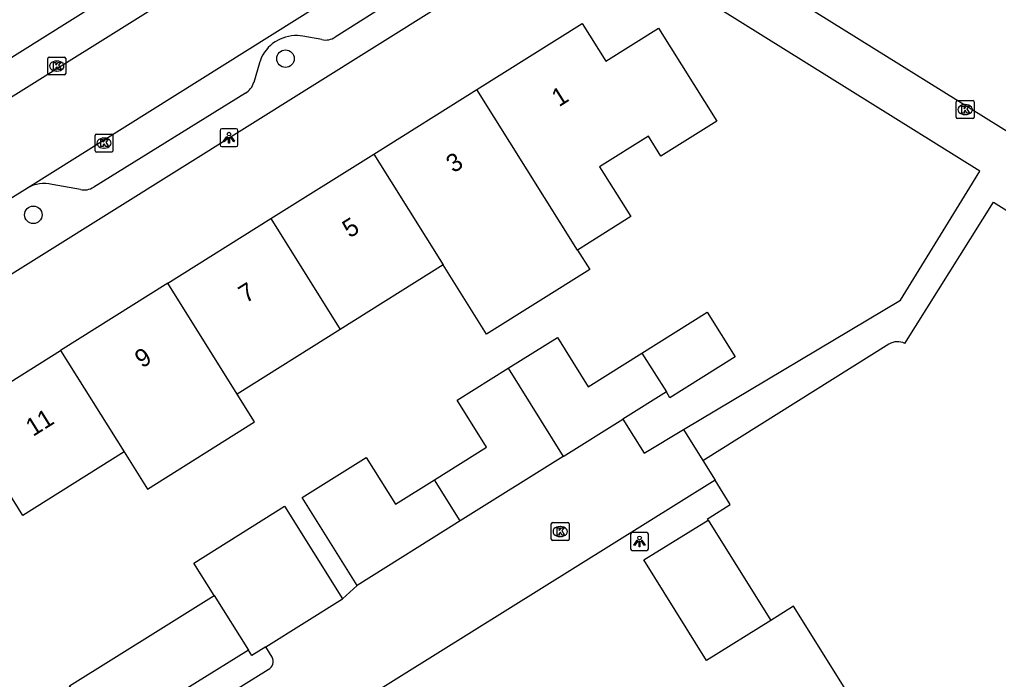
# Model space of a CAD drawing. Extents: x 159353 to 160616, y 385893 to 387321.
# Drawn here: x 159867.4 to 159922.1, y 386134.3 to 386171.1 of the extents above; entities that cross this region are included whole.
import ezdxf

# ---------------------------------------------------------------- set-up
doc = ezdxf.new("R2010")
doc.units = 0
for name, color, linetype in [('IMGEO_Boom', 7, 'Continuous'), ('IMGEO_Kolk', 7, 'Continuous'), ('IMGEO_Lichtpunt', 7, 'Continuous'), ('IMGEO_Pand', 7, 'Continuous'), ('IMGEO_Pand_nummerreeks', 7, 'Continuous'), ('IMGEO_Rijbaan_lokaal_open', 7, 'Continuous'), ('IMGEO_Voetpad_open', 7, 'Continuous')]:
    doc.layers.add(name, color=color, linetype=linetype)

msp = doc.modelspace()

# ---------------------------------------------------------------- linework, layer by layer
at = {"layer": 'IMGEO_Boom'}
for centre in [(159882.287, 386168.961), (159868.209, 386160.245)]:
    msp.add_circle(centre, 0.489, dxfattribs=at)
at = {"layer": 'IMGEO_Kolk'}
for p, q in [((159869.09, 386169.049), (159869.942, 386169.049)), ((159869.015, 386168.123), (159869.015, 386168.975)), ((159869.503, 386168.829), (159869.528, 386168.829)), ((159870.016, 386168.975), (159870.016, 386168.123)), ((159869.942, 386168.049), (159869.09, 386168.049)), ((159869.526, 386168.269), (159869.501, 386168.269)), ((159919.747, 386165.69), (159919.747, 386166.542)), ((159919.822, 386166.616), (159920.674, 386166.616)), ((159920.235, 386166.396), (159920.26, 386166.396)), ((159920.748, 386166.542), (159920.748, 386165.69)), ((159920.258, 386165.836), (159920.233, 386165.836)), ((159920.674, 386165.616), (159919.822, 386165.616)), ((159871.655, 386163.823), (159871.655, 386164.675)), ((159871.73, 386164.749), (159872.582, 386164.749)), ((159872.656, 386164.675), (159872.656, 386163.823)), ((159872.143, 386164.529), (159872.168, 386164.529)), ((159872.582, 386163.749), (159871.73, 386163.749)), ((159872.166, 386163.969), (159872.141, 386163.969)), ((159897.132, 386142.135), (159897.132, 386142.987)), ((159897.207, 386143.061), (159898.059, 386143.061)), ((159897.62, 386142.841), (159897.645, 386142.841)), ((159898.133, 386142.987), (159898.133, 386142.135)), ((159897.643, 386142.281), (159897.618, 386142.281)), ((159898.059, 386142.061), (159897.207, 386142.061))]:
    msp.add_line(p, q, dxfattribs=at)
for points in [[(159869.09, 386169.049), (159869.942, 386169.049)], [(159869.015, 386168.123), (159869.015, 386168.975)], [(159869.336, 386168.749), (159869.459, 386168.749), (159869.459, 386168.598), (159869.589, 386168.749), (159869.753, 386168.749), (159869.607, 386168.598), (159869.76, 386168.349), (159869.608, 386168.349), (159869.523, 386168.513), (159869.459, 386168.446), (159869.459, 386168.349), (159869.336, 386168.349), (159869.336, 386168.749)], [(159870.016, 386168.975), (159870.016, 386168.123)], [(159869.942, 386168.049), (159869.09, 386168.049)], [(159919.747, 386165.69), (159919.747, 386166.542)], [(159919.822, 386166.616), (159920.674, 386166.616)], [(159920.068, 386166.316), (159920.191, 386166.316), (159920.191, 386166.165), (159920.321, 386166.316), (159920.485, 386166.316), (159920.339, 386166.165), (159920.492, 386165.916), (159920.34, 386165.916), (159920.255, 386166.08), (159920.191, 386166.013), (159920.191, 386165.916), (159920.068, 386165.916), (159920.068, 386166.316)], [(159920.748, 386166.542), (159920.748, 386165.69)], [(159920.674, 386165.616), (159919.822, 386165.616)], [(159871.655, 386163.823), (159871.655, 386164.675)], [(159871.73, 386164.749), (159872.582, 386164.749)], [(159872.656, 386164.675), (159872.656, 386163.823)], [(159871.976, 386164.449), (159872.099, 386164.449), (159872.099, 386164.298), (159872.229, 386164.449), (159872.393, 386164.449), (159872.247, 386164.298), (159872.4, 386164.049), (159872.248, 386164.049), (159872.163, 386164.213), (159872.099, 386164.146), (159872.099, 386164.049), (159871.976, 386164.049), (159871.976, 386164.449)], [(159872.582, 386163.749), (159871.73, 386163.749)], [(159897.132, 386142.135), (159897.132, 386142.987)], [(159897.207, 386143.061), (159898.059, 386143.061)], [(159897.453, 386142.761), (159897.576, 386142.761), (159897.576, 386142.61), (159897.706, 386142.761), (159897.87, 386142.761), (159897.724, 386142.61), (159897.877, 386142.361), (159897.725, 386142.361), (159897.64, 386142.525), (159897.576, 386142.458), (159897.576, 386142.361), (159897.453, 386142.361), (159897.453, 386142.761)], [(159898.133, 386142.987), (159898.133, 386142.135)], [(159898.059, 386142.061), (159897.207, 386142.061)]]:
    msp.add_lwpolyline(points, dxfattribs=at)
for centre, start, end in [((159869.092, 386168.973), 91.552, 178.448), ((159869.092, 386168.973), 91.552, 178.448), ((159869.94, 386168.973), 1.552, 88.448), ((159869.94, 386168.973), 1.552, 88.448), ((159869.092, 386168.125), 181.552, 268.448), ((159869.092, 386168.125), 181.552, 268.448), ((159869.94, 386168.125), 271.552, 358.448), ((159869.94, 386168.125), 271.552, 358.448), ((159919.824, 386166.54), 91.552, 178.448), ((159919.824, 386166.54), 91.552, 178.448), ((159920.672, 386166.54), 1.552, 88.448), ((159920.672, 386166.54), 1.552, 88.448), ((159919.824, 386165.692), 181.552, 268.448), ((159919.824, 386165.692), 181.552, 268.448), ((159920.672, 386165.692), 271.552, 358.448), ((159920.672, 386165.692), 271.552, 358.448), ((159871.732, 386164.673), 91.552, 178.448), ((159871.732, 386164.673), 91.552, 178.448), ((159872.58, 386164.673), 1.552, 88.448), ((159872.58, 386164.673), 1.552, 88.448), ((159871.732, 386163.825), 181.552, 268.448), ((159871.732, 386163.825), 181.552, 268.448), ((159872.58, 386163.825), 271.552, 358.448), ((159872.58, 386163.825), 271.552, 358.448), ((159897.209, 386142.985), 91.552, 178.448), ((159897.209, 386142.985), 91.552, 178.448), ((159898.057, 386142.985), 1.552, 88.448), ((159898.057, 386142.985), 1.552, 88.448), ((159897.209, 386142.137), 181.552, 268.448), ((159897.209, 386142.137), 181.552, 268.448), ((159898.057, 386142.137), 271.552, 358.448), ((159898.057, 386142.137), 271.552, 358.448)]:
    msp.add_arc(centre, 0.0765, start, end, dxfattribs=at)
for centre, major_axis, ratio, start_param, end_param in [((159869.502, 386168.549), (-0.387, 0.002), 0.722429, 4.712389, 7.853982), ((159869.527, 386168.549), (-0.39, 0.002), 0.717154, 1.570796, 4.712389), ((159920.234, 386166.116), (-0.387, 0.002), 0.722429, 4.712389, 7.853982), ((159920.259, 386166.116), (-0.39, 0.002), 0.717154, 1.570796, 4.712389), ((159872.142, 386164.249), (-0.387, 0.002), 0.722429, 4.712389, 7.853982), ((159872.167, 386164.249), (-0.39, 0.002), 0.717154, 1.570796, 4.712389), ((159897.619, 386142.561), (-0.387, 0.002), 0.722429, 4.712389, 7.853982), ((159897.644, 386142.561), (-0.39, 0.002), 0.717154, 1.570796, 4.712389)]:
    msp.add_ellipse(centre, major_axis=major_axis, ratio=ratio, start_param=start_param, end_param=end_param, dxfattribs=at)
at = {"layer": 'IMGEO_Lichtpunt'}
for p, q in [((159878.636, 386164.952), (159878.636, 386164.145)), ((159878.636, 386164.952), (159878.636, 386164.145)), ((159879.538, 386165.047), (159878.73, 386165.047)), ((159879.538, 386165.047), (159878.73, 386165.047)), ((159879.632, 386164.145), (159879.632, 386164.952)), ((159879.632, 386164.145), (159879.632, 386164.952)), ((159878.73, 386164.051), (159879.538, 386164.051)), ((159878.73, 386164.051), (159879.538, 386164.051)), ((159901.564, 386142.408), (159901.564, 386141.601)), ((159901.564, 386142.408), (159901.564, 386141.601)), ((159902.466, 386142.503), (159901.658, 386142.503)), ((159902.466, 386142.503), (159901.658, 386142.503)), ((159902.56, 386141.601), (159902.56, 386142.408)), ((159902.56, 386141.601), (159902.56, 386142.408)), ((159901.658, 386141.507), (159902.466, 386141.507)), ((159901.658, 386141.507), (159902.466, 386141.507))]:
    msp.add_line(p, q, dxfattribs=at)
for points in [[(159879.01, 386164.616), (159879.049, 386164.588), (159878.861, 386164.326), (159878.823, 386164.353), (159879.01, 386164.616)], [(159879.222, 386164.588), (159879.26, 386164.615), (159879.447, 386164.353), (159879.408, 386164.325), (159879.222, 386164.588)], [(159879.112, 386164.568), (159879.159, 386164.568), (159879.159, 386164.246), (159879.112, 386164.246), (159879.112, 386164.568)], [(159901.938, 386142.072), (159901.977, 386142.044), (159901.789, 386141.782), (159901.751, 386141.809), (159901.938, 386142.072)], [(159902.04, 386142.024), (159902.087, 386142.024), (159902.087, 386141.702), (159902.04, 386141.702), (159902.04, 386142.024)], [(159902.15, 386142.044), (159902.188, 386142.071), (159902.375, 386141.809), (159902.336, 386141.781), (159902.15, 386142.044)]]:
    msp.add_lwpolyline(points, dxfattribs=at)
for centre in [(159879.135, 386164.75), (159902.063, 386142.206)]:
    msp.add_circle(centre, 0.0994, dxfattribs=at)
for centre, start, end in [((159878.73, 386164.952), 90, 180), ((159878.73, 386164.952), 90, 180), ((159879.538, 386164.952), 0, 90), ((159879.538, 386164.952), 0, 90), ((159878.73, 386164.145), 180, 270), ((159878.73, 386164.145), 180, 270), ((159879.538, 386164.145), 270, 0), ((159879.538, 386164.145), 270, 360), ((159901.658, 386142.408), 90, 180), ((159901.658, 386142.408), 90, 180), ((159902.466, 386142.408), 0, 90), ((159902.466, 386142.408), 0, 90), ((159901.658, 386141.601), 180, 270), ((159901.658, 386141.601), 180, 270), ((159902.466, 386141.601), 270, 0), ((159902.466, 386141.601), 270, 360)]:
    msp.add_arc(centre, 0.0946, start, end, dxfattribs=at)
at = {"layer": 'IMGEO_Pand'}
for points in [[(159892.974, 386167.239), (159898.855, 386170.924), (159900.178, 386168.813), (159903.127, 386170.661), (159906.377, 386165.476), (159903.259, 386163.522), (159902.564, 386164.631), (159899.832, 386162.919), (159901.572, 386160.144), (159898.594, 386158.278)], [(159887.22, 386163.634), (159892.974, 386167.239)], [(159898.594, 386158.278), (159892.974, 386167.239)], [(159881.466, 386160.028), (159887.22, 386163.634)], [(159887.22, 386163.634), (159891.099, 386157.447)], [(159916.885, 386153.064), (159921.823, 386160.953), (159922.729, 386160.385)], [(159875.711, 386156.422), (159881.466, 386160.028)], [(159881.466, 386160.028), (159885.345, 386153.841)], [(159898.594, 386158.278), (159899.279, 386157.186), (159893.523, 386153.579), (159891.099, 386157.447)], [(159891.099, 386157.447), (159885.345, 386153.841)], [(159875.711, 386156.422), (159869.73, 386152.674)], [(159879.59, 386150.235), (159875.711, 386156.422)], [(159902.198, 386152.528), (159905.839, 386154.806), (159907.401, 386152.31), (159903.763, 386150.034), (159903.56, 386150.357)], [(159885.345, 386153.841), (159879.59, 386150.235)], [(159894.719, 386151.673), (159897.472, 386153.395), (159899.19, 386150.646), (159902.198, 386152.528)], [(159873.286, 386147.004), (159867.629, 386143.458), (159864.075, 386149.131), (159869.73, 386152.674)], [(159869.73, 386152.674), (159873.286, 386147.004)], [(159905.588, 386146.53), (159915.99, 386153.031)], [(159902.198, 386152.528), (159903.56, 386150.357)], [(159890.606, 386145.45), (159893.514, 386147.27), (159891.873, 386149.892), (159894.719, 386151.673)], [(159894.719, 386151.673), (159897.803, 386146.754)], [(159873.286, 386147.004), (159874.585, 386144.932), (159880.565, 386148.68), (159879.59, 386150.235)], [(159903.56, 386150.357), (159901.128, 386148.835)], [(159897.803, 386146.754), (159901.128, 386148.835)], [(159886.292, 386139.546), (159883.214, 386144.455), (159886.794, 386146.7), (159888.431, 386144.089), (159890.606, 386145.45)], [(159897.803, 386146.754), (159892.047, 386143.151)], [(159905.588, 386146.53), (159906.28, 386145.421)], [(159892.047, 386143.151), (159890.606, 386145.45)], [(159905.904, 386143.202), (159905.861, 386143.271), (159905.944, 386143.322), (159907.128, 386144.061), (159906.28, 386145.421)], [(159878.306, 386138.994), (159877.173, 386140.803), (159882.231, 386143.974), (159885.469, 386138.81)], [(159892.047, 386143.151), (159886.292, 386139.546)], [(159909.392, 386137.597), (159905.803, 386135.363), (159902.311, 386140.975), (159905.904, 386143.202)], [(159905.904, 386143.202), (159909.392, 386137.597)], [(159872.146, 386130.889), (159870.235, 386133.94), (159875.321, 386137.125), (159878.306, 386138.994)], [(159878.306, 386138.994), (159880.219, 386135.944)], [(159881.188, 386136.126), (159885.469, 386138.81)], [(159932.111, 386105.92), (159931.024, 386107.659), (159930.202, 386107.144), (159910.666, 386138.39), (159909.392, 386137.597)], [(159880.219, 386135.944), (159877.232, 386134.074), (159872.146, 386130.889)], [(159881.188, 386136.126), (159880.41, 386135.639), (159880.219, 386135.944)]]:
    msp.add_lwpolyline(points, dxfattribs=at)
msp.add_arc((159916.47, 386152.16), 0.994, 65.342, 118.8813, dxfattribs=at)
at = {"layer": 'IMGEO_Rijbaan_lokaal_open'}
for points in [[(159907.73, 386192.277), (159863.686, 386164.764)], [(159867.882, 386161.754), (159910.272, 386188.323)], [(159858.347, 386155.828), (159867.882, 386161.754)], [(159901.128, 386148.835), (159902.313, 386146.942), (159904.513, 386148.252)], [(159904.513, 386148.252), (159905.588, 386146.53)], [(159906.28, 386145.421), (159882.976, 386130.886)], [(159885.469, 386138.81), (159886.292, 386139.546)], [(159881.549, 386135.549), (159881.188, 386136.126)], [(159870.116, 386127.9), (159881.331, 386134.855)]]:
    msp.add_lwpolyline(points, dxfattribs=at)
msp.add_arc((159881.076, 386135.316), 0.527, 298.9037, 26.2191, dxfattribs=at)
at = {"layer": 'IMGEO_Voetpad_open'}
for points in [[(159864.259, 386165.766), (159864.604, 386167.306), (159864.784, 386167.671), (159904.106, 386192.314)], [(159915.414, 386187.292), (159919.465, 386186.776), (159936.608, 386162.243), (159937.142, 386161.478), (159940.626, 386156.491), (159940.19, 386155.797), (159939.355, 386154.471), (159904.863, 386175.937)], [(159898.457, 386176.619), (159857.761, 386151.157)], [(159904.513, 386148.252), (159916.642, 386155.476), (159920.506, 386161.777), (159921.061, 386162.682), (159904.122, 386173.254), (159904.012, 386173.093), (159900.14, 386175.506)], [(159890.88, 386173.845), (159885.066, 386170.167)], [(159884.324, 386170.027), (159883.252, 386170.216), (159882.96, 386170.245)], [(159880.885, 386168.879), (159880.829, 386168.719), (159880.527, 386167.639)], [(159880.049, 386167.033), (159871.578, 386161.795)], [(159870.836, 386161.655), (159869.251, 386161.935)]]:
    msp.add_lwpolyline(points, dxfattribs=at)
for centre, radius, start, end in [((159882.887, 386168.097), 2.15, 88.0568, 158.6581), ((159884.54, 386170.917), 0.916, 256.3529, 305.017), ((159879.486, 386167.969), 1.092, 301.0481, 342.4207), ((159868.799, 386160.085), 1.905, 76.2773, 118.7859), ((159871.05, 386162.556), 0.927, 256.638, 304.7318)]:
    msp.add_arc(centre, radius, start, end, dxfattribs=at)

# ---------------------------------------------------------------- texts
at = {"layer": 'IMGEO_Pand_nummerreeks'}
for s, rotation, p in [('1', 32.0711, (159897.561, 386166.242)), ('3', 32.0711, (159891.668, 386162.55)), ('5', 32.0711, (159885.871, 386158.918)), ('7', 32.0711, (159880.074, 386155.286)), ('9', 32.0684, (159874.278, 386151.654)), ('11', 32.0684, (159868.188, 386147.839))]:
    msp.add_text(s, height=1, rotation=rotation, dxfattribs=at).set_placement(p)

doc.saveas('drawing.dxf')
